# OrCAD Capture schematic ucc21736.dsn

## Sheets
1 PAGE1: size E
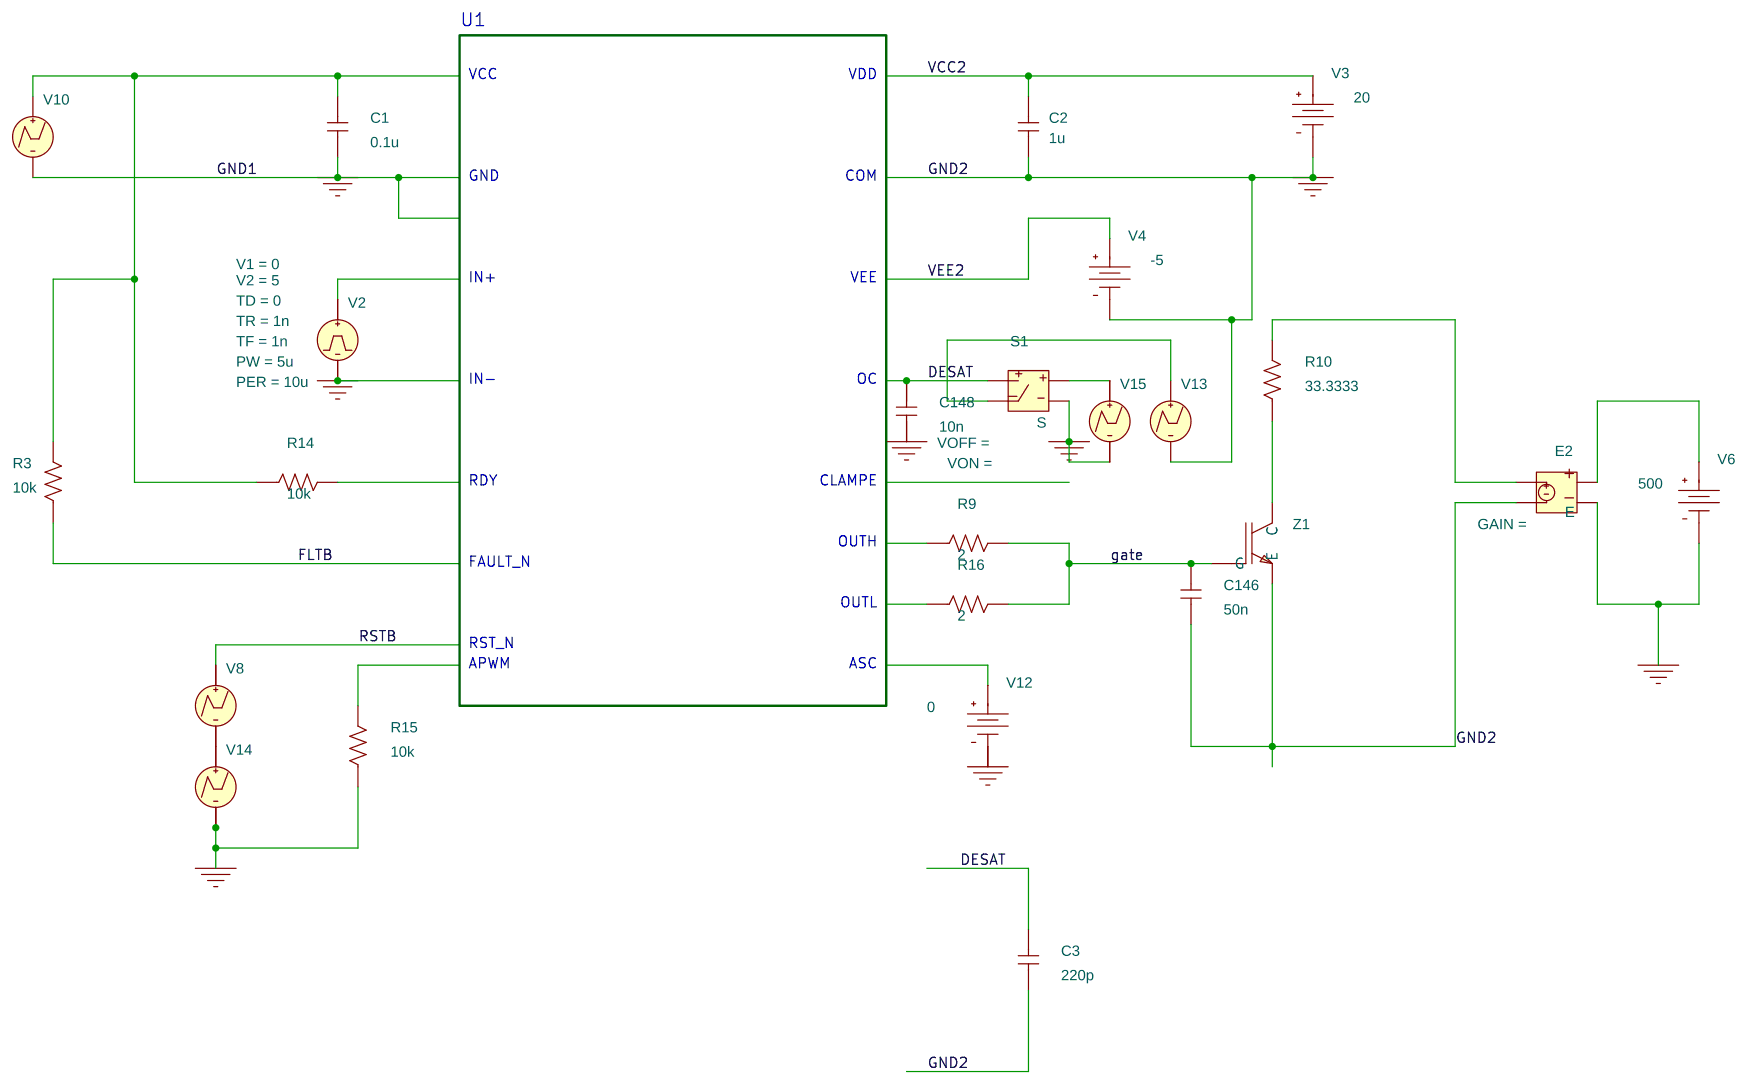
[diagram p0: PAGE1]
2 ISO5851_TRANS: size E; block U1
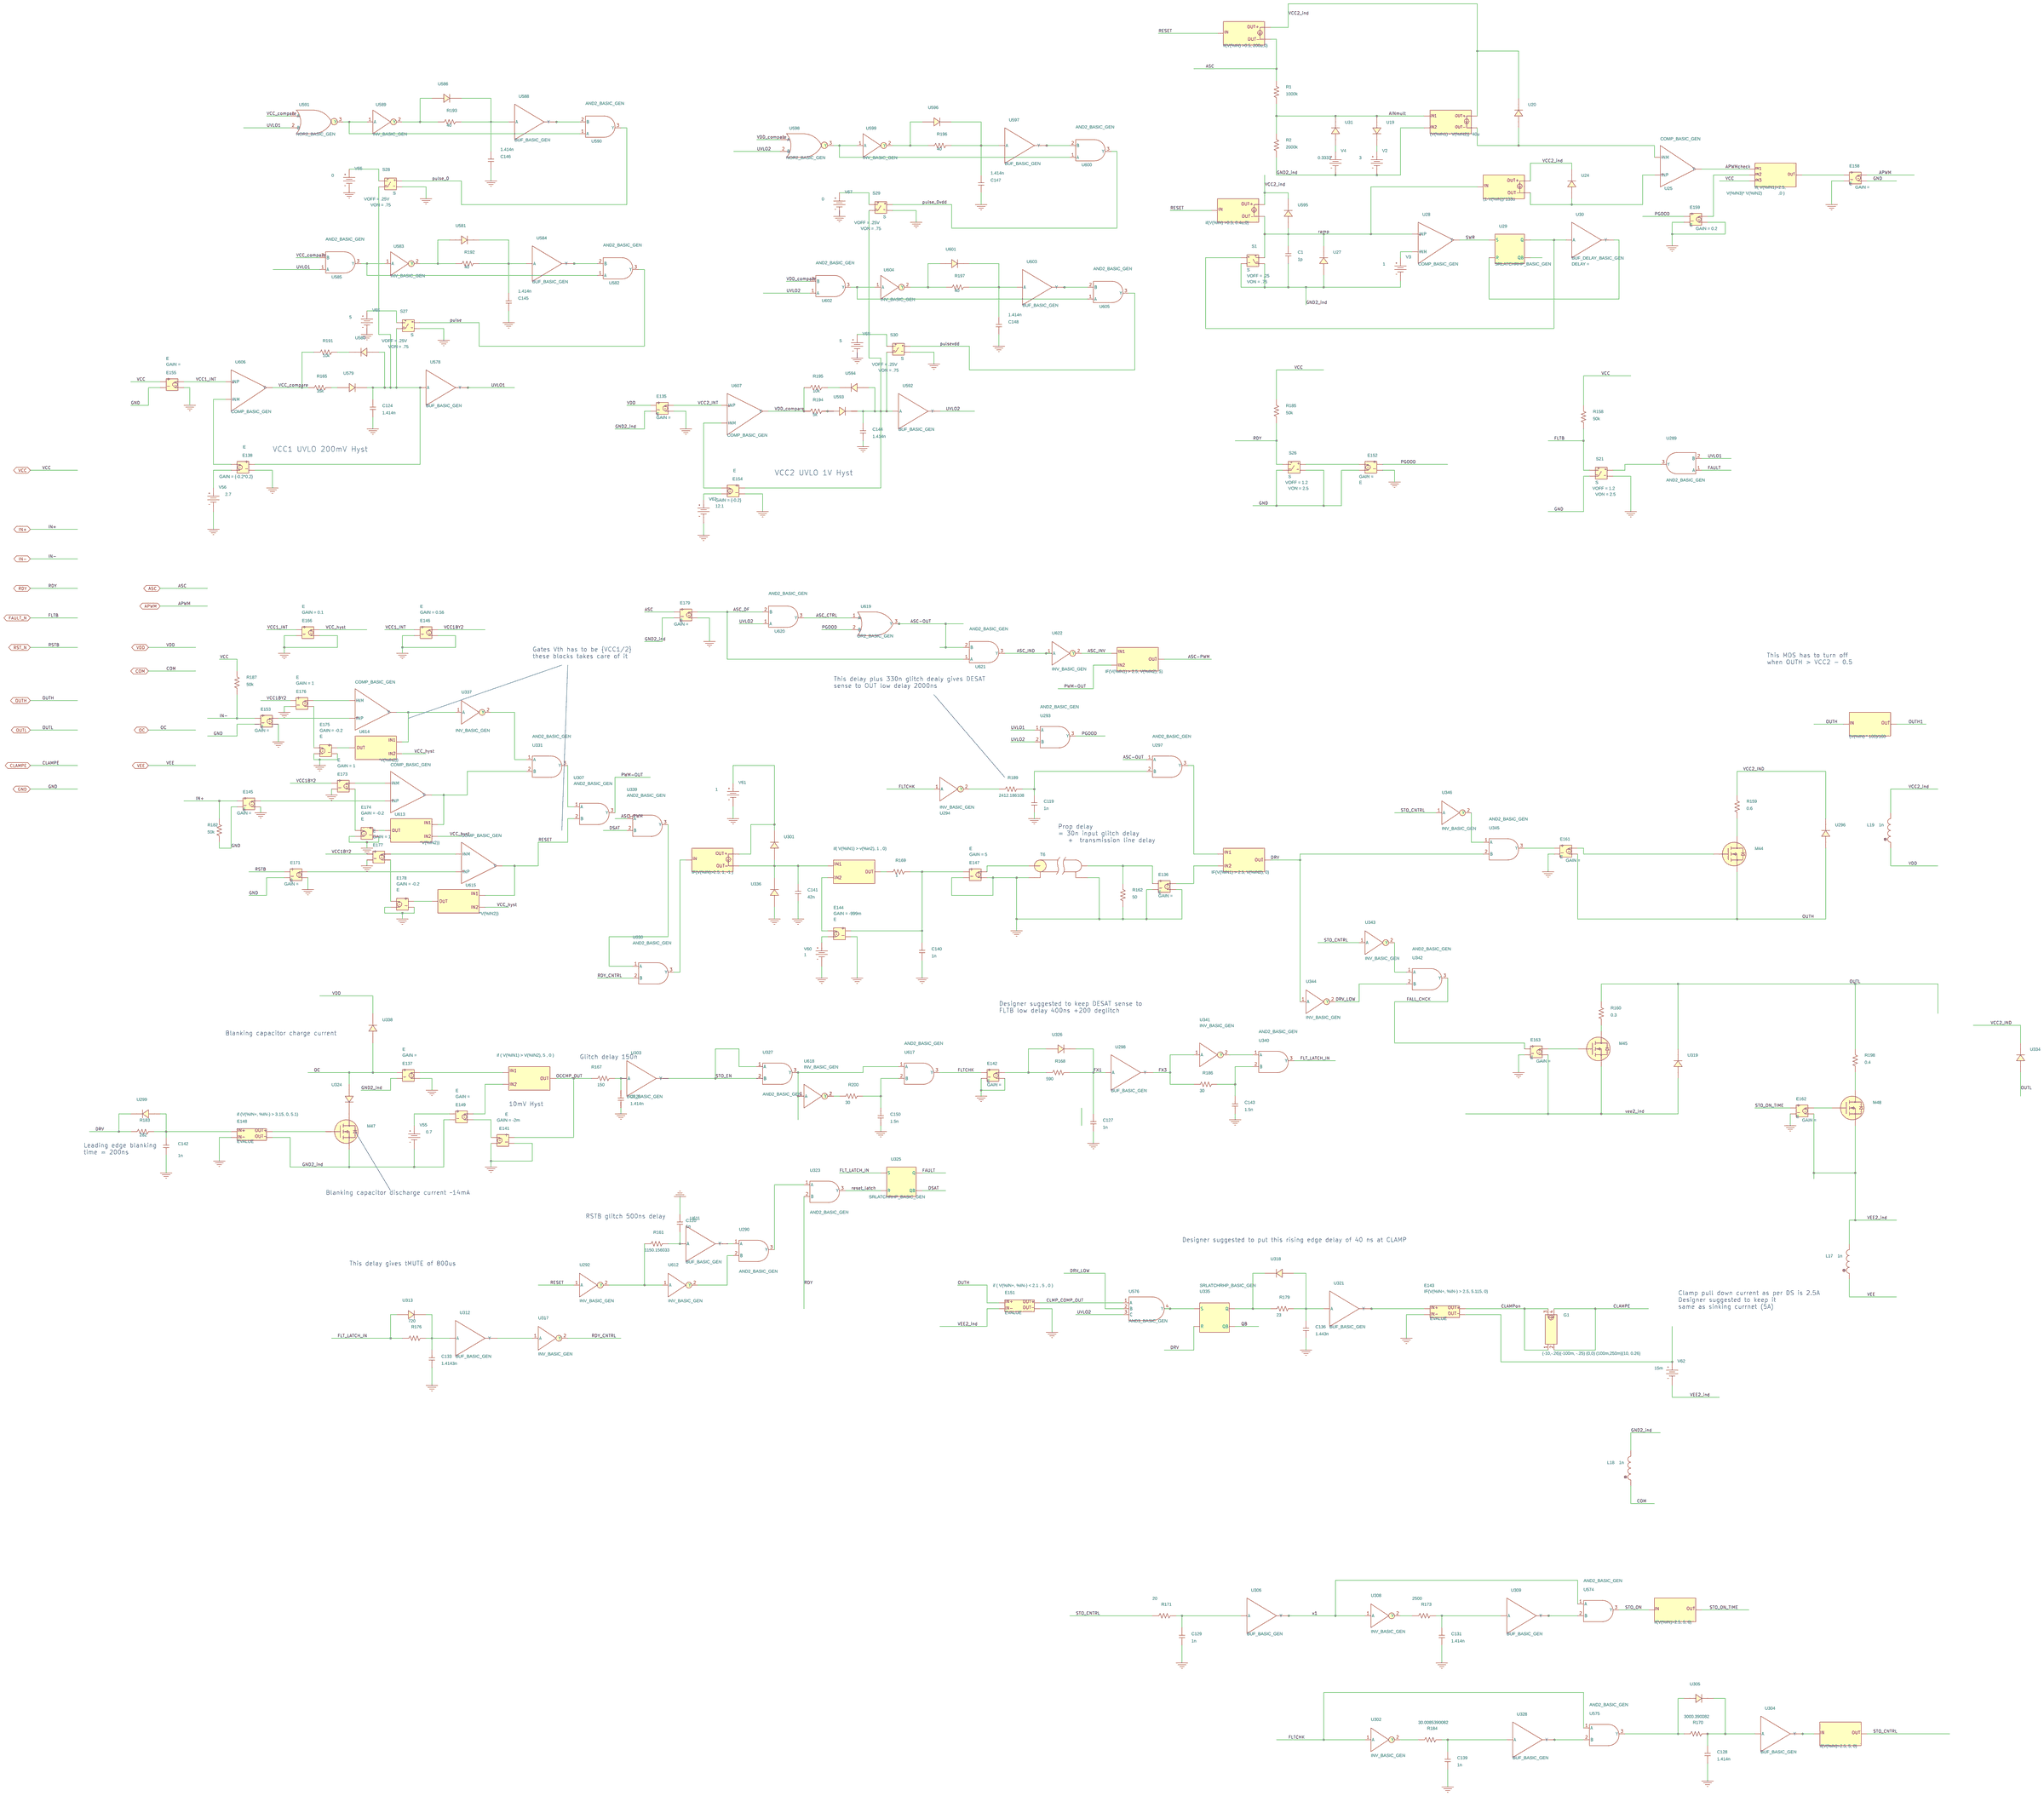
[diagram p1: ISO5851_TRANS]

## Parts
sheet ISO5851_TRANS
ABM2I1  ABM2I
ABM67  ABM2
ABM70  ABM1
ABM71  ABM2
ABM74  ABM1
ABM79  ABM2
ABM80  ABM1
ABM81  ABM3
ABM82  ABM2
ABM83  ABM2
ABM84  ABM2
ABM85  ABM2
ABMII1  ABMII
ABMII2  ABMII
ABMII3  ABMII
ABMII12  ABMII
C1#2  1p  [RAD/CK05]
C119  1n  [RAD/CK05]
C120  1n  [RAD/CK05]
C123  1.414n  [RAD/CK05]
C124  1.414n  [RAD/CK05]
C127  1n  [RAD/CK05]
C128  1.414n  [RAD/CK05]
C129  1n  [RAD/CK05]
C131  1.414n  [RAD/CK05]
C133  1.4143n  [RAD/CK05]
C136  1.443n  [RAD/CK05]
C139  1n  [RAD/CK05]
C140  1n  [RAD/CK05]
C141  42n  [RAD/CK05]
C142  1n  [RAD/CK05]
C143  1.5n  [RAD/CK05]
C144  1.414n  [RAD/CK05]
C145  1.414n  [RAD/CK05]
C146#2  1.414n  [RAD/CK05]
C147  1.414n  [RAD/CK05]
C148#2  1.414n  [RAD/CK05]
C150  1.5n  [RAD/CK05]
E135  E
E136  E
E137  E
E138  E
E141  E
E142  E
E143  EVALUE
E144  E
E145  E
E146  E
E147  E
E148  EVALUE
E149  E
E151  EVALUE
E152  E
E153  E
E154  E
E155  E
E158  E
E159  E
E161  E
E162  E
E163  E
E166  E
E171  E
E173  E
E174  E
E175  E
E176  E
E177  E
E178  E
E179  E
G1  GTABLE
L17  1n  [DISC/.350x.175/LS.200x.100/.034]
L18  1n  [DISC/.350x.175/LS.200x.100/.034]
L19  1n  [DISC/.350x.175/LS.200x.100/.034]
M44  DMG4800LSD
M45  DMG4800LSD
M47  DMG4800LSD
M48  DMG4800LSD
R1  1000k  [AX/RC05]
R2  2000k  [AX/RC05]
R158  50k  [AX/RC05]
R159  0.6  [AX/RC05]
R160  0.3  [AX/RC05]
R161  1150.156033  [AX/RC05]
R162  50  [AX/RC05]
R165  35k  [AX/RC05]
R167  150  [AX/RC05]
R168  590  [AX/RC05]
R169  1  [AX/RC05]
R170  3000.390082  [AX/RC05]
R171  20  [AX/RC05]
R173  2500  [AX/RC05]
R176  720  [AX/RC05]
R179  23  [AX/RC05]
R182  50k  [AX/RC05]
R183  282  [AX/RC05]
R184  30.0085390082  [AX/RC05]
R185  50k  [AX/RC05]
R186  30  [AX/RC05]
R187  50k  [AX/RC05]
R189  2412.186108  [AX/RC05]
R191  10k  [AX/RC05]
R192  40  [AX/RC05]
R193  40  [AX/RC05]
R194  5k  [AX/RC05]
R195  10k  [AX/RC05]
R196  40  [AX/RC05]
R197  40  [AX/RC05]
R198  0.4  [AX/RC05]
R200  30  [AX/RC05]
S1#2  S
S21  S
S26  S
S27  S
S28  S
S29  S
S30  S
T6  T
U19  D_D1
U20  D_D1
U24  D_D1
U25  COMP_BASIC_GEN
U27  D_D1
U28  COMP_BASIC_GEN
U29  SRLATCHRHP_BASIC_GEN
U30  BUF_DELAY_BASIC_GEN
U31  D_D1
U289  AND2_BASIC_GEN
U290  AND2_BASIC_GEN
U292  INV_BASIC_GEN
U293  AND2_BASIC_GEN
U294  INV_BASIC_GEN
U296  D_D1
U297  AND2_BASIC_GEN
U298  BUF_BASIC_GEN
U299  D_D1
U301  D_D1
U302  INV_BASIC_GEN
U303  BUF_BASIC_GEN
U304  BUF_BASIC_GEN
U305  D_D1
U306  BUF_BASIC_GEN
U307  AND2_BASIC_GEN
U308  INV_BASIC_GEN
U309  BUF_BASIC_GEN
U312  BUF_BASIC_GEN
U313  D_D1
U317  INV_BASIC_GEN
U318  D_D1
U319  D_D1
U321  BUF_BASIC_GEN
U323  AND2_BASIC_GEN
U324  D_D1
U325  SRLATCHRHP_BASIC_GEN
U326  D_D1
U327  AND2_BASIC_GEN
U328  BUF_BASIC_GEN
U330  AND2_BASIC_GEN
U331  AND2_BASIC_GEN
U334  D_D1
U335  SRLATCHRHP_BASIC_GEN
U336  D_D1
U337  INV_BASIC_GEN
U338  D_D1
U339  AND2_BASIC_GEN
U340  AND2_BASIC_GEN
U341  INV_BASIC_GEN
U342  AND2_BASIC_GEN
U343  INV_BASIC_GEN
U344  INV_BASIC_GEN
U345  AND2_BASIC_GEN
U346  INV_BASIC_GEN
U574  AND2_BASIC_GEN
U575  AND2_BASIC_GEN
U576  AND3_BASIC_GEN
U578  BUF_BASIC_GEN
U579  D_D1
U580  D_D1
U581  D_D1
U582  AND2_BASIC_GEN
U583  INV_BASIC_GEN
U584  BUF_BASIC_GEN
U585  AND2_BASIC_GEN
U586  D_D1
U588  BUF_BASIC_GEN
U589  INV_BASIC_GEN
U590  AND2_BASIC_GEN
U591  NOR2_BASIC_GEN
U592  BUF_BASIC_GEN
U593  D_D1
U594  D_D1
U595  D_D1
U596  D_D1
U597  BUF_BASIC_GEN
U598  NOR2_BASIC_GEN
U599  INV_BASIC_GEN
U600  AND2_BASIC_GEN
U601  D_D1
U602  AND2_BASIC_GEN
U603  BUF_BASIC_GEN
U604  INV_BASIC_GEN
U605  AND2_BASIC_GEN
U606  COMP_BASIC_GEN
U607  COMP_BASIC_GEN
U611  BUF_BASIC_GEN
U612  INV_BASIC_GEN
U613  COMP_BASIC_GEN
U614  COMP_BASIC_GEN
U615  COMP_BASIC_GEN
U617  AND2_BASIC_GEN
U618  INV_BASIC_GEN
U619  OR2_BASIC_GEN
U620  AND2_BASIC_GEN
U621  AND2_BASIC_GEN
U622  INV_BASIC_GEN
V3#2  VDC
V4#2  VDC
V55  VDC
V56  VDC
V60  VDC
V61  VDC
V62  VDC
V63  VDC
V65  VDC
V66  VDC
V67  VDC
V68  VDC
sheet PAGE1
C1  0.1u  [RAD/CK05]
C2  1u  [RAD/CK05]
C3  220p  [RAD/CK05]
C146  50n  [RAD/CK05]
C148  10n  [cap196]
E2  E
R3  10k  [AX/RC05]
R9  2  [AX/RC05]
R10  33.3333  [AX/RC05]
R14  10k  [AX/RC05]
R15  10k  [AX/RC05]
R16  2  [AX/RC05]
S1  S
V2  VPULSE
V3  VDC
V4  VDC
V6  VDC
V8  VPWL
V10  VPWL
V12  VDC
V13  VPWL
V14  VPWL
V15  VPWL
Z1  IXGA8N100  [TO-263]

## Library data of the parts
ABM2I1 = ABM2_I: EXP1: (V(%IN1) - V(%IN2)) *40u
ABM67 = ABM2: EXP1: if ( V(%IN1) > V(%IN2), 5 , 0 )
ABM70 ABM74 = ABM1: EXP1: if(V(%IN)>2.5, 5, 0)
ABM71 = ABM2: EXP1: if( V(%IN1) > v(%in2), 1 , 0)
ABM79 = ABM2: EXP1: IF(V(%IN1) > 2.5, V(%IN2), 0)
ABM80 = ABM1: EXP1: (V(%IN) * 100)/100
ABM81 = ABM3: EXP1: if( V(%IN1)>2.5,; EXP2: V(%IN3)* V(%IN2); EXP3: ,0 )
ABM82-ABM84 = ABM2: EXP2: *V(%IN2))
ABM85 = ABM2: EXP1: IF(V(%IN1) > 2.5, V(%IN2), 5)
ABMII1 = ABM1_I: EXP1: if(V(%IN) >0.5, 200u,0)
ABMII2 = ABM1_I: EXP1: if(V(%IN) >0.5, 0.4u,0)
ABMII3 = ABM1_I: EXP1: (1-V(%IN))*133u
ABMII12 = ABM1_I: EXP1: IF(V(%IN)>2.5, 1, -1 )
C1 C1#2 C2 C3 C119 C120 C123 C124 C127 C136 C140-C146 C146#2 C147 C148 C148#2 C150 = C
C128 C129 C131 C133 C139 = C: IC: .000001
E2 E135-E137 E142 E145 E149 E152 E153 E155 E158 E161-E163 E171 E179 = E
E138 = E: GAIN: {-0.2*0.2}
E141 = E: GAIN: -2m
E143 = EVALUE: EXPR: IF(V(%IN+, %IN-) > 2.5, 5.115, 0)
E144 = E: GAIN: -999m
E146 = E: GAIN: 0.56
E147 = E: GAIN: 5
E148 = EVALUE: EXPR: if (V(%IN+, %IN-) > 3.15, 0, 5.1)
E151 = EVALUE: EXPR: if ( V(%IN+, %IN-) < 2.1 , 5 , 0 )
E154 = E: GAIN: {-0.2}
E159 = E: GAIN: 0.2
E166 = E: GAIN: 0.1
E173 E176 E177 = E: GAIN: 1
E174 E175 E178 = E: GAIN: -0.2
G1 = GTABLE: TABLE: (-10,-.26)(-100m, -.25) (0,0) (100m,250m)(10, 0.26)
L17-L19 = L
M44 M45 M47 M48 = NAMS20: PSpiceTemplate: X^@REFDES  %D %G %S @MODEL
R1 R2 = r
R3 R9 R10 R14-R16 R158-R162 R165 R167-R171 R173 R176 R179 R182-R187 R189 R191-R198 R200 = R
S1#2 = S: ROFF: 1e9; RON: 1.0m; VOFF: .25; VON: .75
S21 = S: ROFF: 1G; RON: 1m; VOFF: 1.2; VON: 2.5
S26 = S: ROFF: 1m; RON: 1G; VOFF: 1.2; VON: 2.5
S27-S30 = S: VOFF: .25V; VON: .75
T6 = T: TD: 46n; Z0: 50
U19 U20 U24 U27 U31 U296 U299 U301 U305 U313 U318 U319 U324 U326 U334 U336 U338 U579-U581 U586 U593-U596 U601 = D_D1
U25 = COMP_BASIC_GEN_2: VDD: 5; VTHRESH: 2.5
U28 = COMP_BASIC_GEN_5
U29 = SRLATCHRHP_BASIC_GEN
U30 = BUF_DELAY_BASIC_GEN
U289 U290 U293 U297 U307 U323 U327 U330 U331 U339 U340 U342 U345 U574 U575 U582 U585 U590 U600 U602 U605 U617 U620 U621 = AND2_BASIC_GEN: VDD: 5; VTHRESH: 2.5
U292 U294 U302 U308 U317 U337 U341 U343 U344 U346 U583 U589 U599 U604 U612 U618 U622 = INV_BASIC_GEN: VDD: 5; VTHRESH: 2.5
U298 = BUF_BASIC_GEN_5: VDD: 5; VTHRESH: 2.5
U303 = BUF_BASIC_GEN_8: VDD: 5; VTHRESH: 2.5
U304 = BUF_BASIC_GEN_11: VDD: 5; VTHRESH: 2.5
U306 = BUF_BASIC_GEN_13: VDD: 5; VTHRESH: 2.5
U309 = BUF_BASIC_GEN_9: VDD: 5; VTHRESH: 2.5
U312 = BUF_BASIC_GEN_2: VDD: 5; VTHRESH: 2.5
U321 = BUF_BASIC_GEN_10: VDD: 5; VTHRESH: 2.5
U325 = SRLATCHRHP_BASIC_GEN_1: VDD: 5; VTHRESH: 2.5
U328 = BUF_BASIC_GEN_3: VDD: 5; VTHRESH: 2.5
U335 = SRLATCHRHP_BASIC_GEN_2: VDD: 5; VTHRESH: 2.5
U576 = AND3_BASIC_GEN: VDD: 5; VTHRESH: 2500E-3
U578 = BUF_BASIC_GEN_14: VDD: 5; VTHRESH: 2.5
U584 = BUF_BASIC_GEN_12: VDD: 5; VTHRESH: 2.5
U588 = BUF_BASIC_GEN_6: VDD: 5; VTHRESH: 2.5
U591 U598 = NOR2_BASIC_GEN: VDD: 5; VTHRESH: 2.5
U592 = BUF_BASIC_GEN: VDD: 5; VTHRESH: 2.5
U597 = BUF_BASIC_GEN_4: VDD: 5; VTHRESH: 2.5
U603 = BUF_BASIC_GEN_7: VDD: 5; VTHRESH: 2.5
U606 = COMP_BASIC_GEN_1: VDD: 5; VTHRESH: 2.5
U607 = COMP_BASIC_GEN_3: VDD: 5; VTHRESH: 2.5
U611 = BUF_BASIC_GEN_1: VDD: 5; VTHRESH: 2.5
U613 = COMP_BASIC_GEN: VDD: 5; VTHRESH: 2.5
U614 = COMP_BASIC_GEN_4: VDD: 5; VTHRESH: 2.5
U615 = COMP_BASIC_GEN_6: VDD: 5; VTHRESH: 2.5
U619 = OR2_BASIC_GEN: PSpiceTemplate: X^@REFDES %A %B %Y @MODEL PARAMS: ?VDD|VDD=@VDD||VDD=1| ?VSS|VSS=@VSS||VSS=0| ?VTHRESH|VTHRESH=@VTHRESH||VTHRESH=0.5|; VDD: 5
V3#2 V60 V61 = VDC: DC: 1
V4#2 = VDC: DC: 0.3333
V55 = VDC: DC: 0.7
V56 = VDC: DC: 2.7
V62 = VDC: DC: 15m
V63 = VDC: DC: 12.1
V65 V68 = VDC: DC: 5
V12 V66 V67 = VDC: DC: 0
S1 = S
V2 = VPULSE: PER: 10u; PW: 5u; TD: 0; TF: 1n; TR: 1n; V1: 0; V2: 5
V3 = VDC: DC: 20
V4 = VDC: DC: -5
V6 = VDC: DC: 500
V8 = VPWL: PSpiceTemplate: V^@REFDES %+ %- ?DC|DC @DC| ?AC|AC @AC|\n+PWL @T1 @V1 @T2 @V2 #T3/@T3 @V3/ #T4/@T4 @V4/ #T5/@T5 @V5/ #T6/@T6 @V6/ #T7/@T7 @V7/ #T8/@T8 @V8/ #T9/@T9 @V9/ #T10/@T10 @V10/; T1: 0; T2: 44.4u; T3: 44.401u; T4: 44.8u; T5: 44.801u; T6: 65u; T7: 65.001u; T8: 85u; V1: 5; V2: 5; V3: 0; V4: 0; V5: 5; V6: 5; V7: 0; V8: 0
V10 = VPWL: PSpiceTemplate: V^@REFDES %+ %- ?DC|DC @DC| ?AC|AC @AC|\n+PWL @T1 @V1 @T2 @V2 #T3/@T3 @V3/ #T4/@T4 @V4/ #T5/@T5 @V5/ #T6/@T6 @V6/ #T7/@T7 @V7/ #T8/@T8 @V8/ #T9/@T9 @V9/ #T10/@T10 @V10/; T1: 0; T2: 1u; V1: 0; V2: 5
V13 = VPWL: T1: 40u; T2: 45u; V1: 0; V2: 1
V14 = VPWL: PSpiceTemplate: V^@REFDES %+ %- ?DC|DC @DC| ?AC|AC @AC|\n+PWL @T1 @V1 @T2 @V2 #T3/@T3 @V3/ #T4/@T4 @V4/ #T5/@T5 @V5/ #T6/@T6 @V6/ #T7/@T7 @V7/ #T8/@T8 @V8/ #T9/@T9 @V9/ #T10/@T10 @V10/; T1: 0; T2: 66u; T3: 66.001u; V1: 0; V2: 0; V3: 5
V15 = VPWL: T1: 45u; T2: 46u; T3: 46.01u; V1: 1; V2: 1; V3: 0
Z1 = IXGA8N100

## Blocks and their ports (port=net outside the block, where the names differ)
U1 = schematic UCC21736_TRANS, on sheet PAGE1: RDY=N16432057, IN+=N16431787, IN-=0, OUTH=N16432123, OUTL=N16432177, FAULT_N=FLTB, RST_N=RSTB, GND=0, VEE=VEE2, COM=0, VDD=VCC2, VCC=N16431547, OC=DESAT, APWM=N16432213, CLAMPE=N16432063, ASC=N16432223

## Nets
U1/VCC1_INT: E146.1 E155.3 E166.1 U606.INP
U1/VCC1BY2: E146.3 E173.1 E176.1 E177.1
U1/VCC2_IND: ABM2I1.3(OUT+) ABMII1.2(out+) ABMII2.2(out+) ABMII3.2(out+) L19.2 R159.2 U20.2(C) U24.2(C) U296.2(C) U334.2(C) U595.2(C)
U1/VCC2_INT: E135.3 U607.INP
U1/VCC_compare: R165.1 R191.1 U585.2(B) U591.1(A) U606.Y
U1/VCC_hyst: ABM82.2(IN2) ABM83.2(IN2) ABM84.2(IN2) E166.3
U1/VDD_compare: R194.1 R195.1 U598.1(A) U602.2(B) U607.Y
U1/VEE2_ind: E151.2(IN-) E162.4 E163.4 L17.2 M45.3(S) M48.3(S) U319.1(A) V62.1(-)
VCC2: C2.2 E135.1 L19.1 U338.2(C) V3.0(+)
VEE2: L17.1 V4.0(+)
0: C1.1 C2.1 C3.1 C119.1 C120.1 C123.1 C124.1 C127.1 C128.1 C129.1 C131.1 C133.1 C136.1 C139.1 C140.1 C141.2 C142.1 C143.1 C144.1 C145.2 C146.2 C146#2.2 C147.2 C148.2 C148#2.2 C150.1 E2.2 E2.4 E135.4 E136.2 E136.4 E137.4 E138.2 E141.2 E141.4 E142.2 E142.4 E143.2(IN-) E144.2 E145.2 E145.4 E146.2 E146.4 E147.2 E147.4 E148.2(IN-) E151.4(OUT-) E152.2 E152.4 E153.1 E153.2 E153.4 E154.2 E155.2 E155.4 E158.2 E158.4 E159.2 E159.4 E161.2 E162.2 E163.2 E166.2 E166.4 E171.2 E171.4 E173.2 E174.2 E174.4 E175.2 E175.4 E176.2 E177.2 E178.2 E178.4 E179.4 L18.1 R15.1 R162.1 R182.1 R187.1 S1.1(2) S21.1(2) S21.3(4) S26.1(2) S26.3(4) S27.1(2) S28.1(2) S29.1(2) S30.1(2) T6.2(A-) T6.4(B-) U336.1(A) V2.2(-) V3.1(-) V4.1(-) V6.1(-) V10.2(-) V12.1(-) V13.2(-) V14.2(-) V15.2(-) V56.1(-) V60.1(-) V61.1(-) V63.1(-) V65.1(-) V66.1(-) V67.1(-) V68.1(-) Z1.3(E)
DESAT: C3.2 C148.1 E137.1 S1.2(3) U324.1(A) U338.1(A)
FLTB: R3.1 R158.1 S21.2(3)
gate: C146.1 R9.2 R16.2 Z1.1(G)
RSTB: E171.1 V8.1(+)
U1/AINmult: ABM2I1.1(IN1) R1.1 R2.2 U19.1(A) U31.2(C)
U1/APWMcheck: ABM81.1(IN1) U25.Y
U1/ASC-OUT: U297.1(A) U619.3(Y) U621.2(B)
U1/ASC-PWM: ABM85.3(OUT) U339.1(A)
U1/ASC_CTRL: U619.1(A) U620.3(Y)
U1/ASC_DF: E179.3 U620.2(B) U621.1(A)
U1/ASC_IND: U621.3(Y) U622.1(A)
U1/ASC_INV: ABM85.1(IN1) U622.2(Y)
U1/CLAMPon: E143.3(OUT+) G1.1(IN+) G1.3(OUT+)
U1/CLMP_COMP_OUT: E151.3(OUT+) U576.1(A)
U1/DRV: ABM79.3(OUT) R183.1 U299.2(C) U335.R U344.1(A) U345.2(B)
U1/DRV_LOW: U342.2(B) U344.2(Y) U576.2(B)
U1/DSAT: U325.QB U339.2(B)
U1/FALL_CHCK: E163.1 U342.3(Y)
U1/FAULT: U289.1(A) U325.Q
U1/FLT_LATCH_IN: R176.1 U313.1(A) U325.S U340.3(Y)
U1/FLTCHK: E142.1 U294.1(A) U302.1(A) U575.1(A) U617.3(Y)
U1/FX1: C127.2 R168.2 U298.A U326.2(C)
U1/FX3: R186.1 U298.Y U341.1(A)
U1/OCCMP_OUT: ABM67.3(OUT) E141.1 R167.1
U1/OUTH1: ABM80.2(OUT)
U1/PGOOD: E152.1 E159.1 U293.3(Y) U619.2(B)
U1/pulse: S27.0(1) U582.3(Y)
U1/pulse_0: S28.0(1) U590.3(Y)
U1/pulse_0vdd: S29.0(1) U600.3(Y)
U1/pulsevdd: S30.0(1) U605.3(Y)
U1/PWM-OUT: ABM85.2(IN2) U307.3(Y)
U1/QB: U335.QB
U1/ramp: ABMII2.3(out-) ABMII3.1(IN) C1#2.1 S1#2.2(3) U27.2(C) U28.INP U595.1(A)
U1/RDY_CNTRL: U317.2(Y) U330.2(B)
U1/RESET: ABM84.1(IN1) ABMII1.1(IN) ABMII2.1(IN) U292.1(A) U307.2(B) U615.Y
U1/reset_latch: U323.3(Y) U325.R
U1/STO_CNTRL: ABM70.2(OUT) R171.1 U343.1(A) U346.1(A)
U1/STO_EN: U303.Y U327.1(A) U327.2(B)
U1/STO_ON: ABM74.1(IN) U574.3(Y)
U1/STO_ON_TIME: ABM74.2(OUT) E162.1
U1/SWR: U28.Y U29.S
U1/UVLO1: U289.2(B) U293.1(A) U578.Y U585.1(A) U591.2(B)
U1/UVLO2: U293.2(B) U576.3(C) U592.Y U598.2(B) U602.1(A) U620.1(A)
U1/x1: U306.Y U308.1(A) U574.1(A)
N16431547: ABM81.3(IN3) C1.2 E155.1 R3.2 R14.1 R158.2 R185.2 R187.2 V10.1(+)
N16431787: ABM2I1.2(IN2) C1#2.2 E135.2 E137.2 E145.1 E148.4(OUT-) E149.2 E179.2 L18.2 M47.3(S) R2.1 R182.2 S1#2.1(2) S1#2.3(4) U27.1(A) V2.1(-) V3#2.1(-) V4#2.1(-) V55.1(-)
N16431855: E2.3 R10.2
N16431941: E2.1 V6.0(+)
N16431955: R10.1 Z1.2(C)
N16432057: R14.2 R185.1 S26.2(3) U323.2(B)
N16432063: G1.2(IN-) G1.4(OUT-)
N16432123: ABM80.1(IN) E151.1(IN+) E161.4 M44.3(S) R9.1 U296.1(A)
N16432177: R16.1 R160.2 R198.2 U319.2(C) U334.1(A)
N16432213: E158.3 R15.2
N16432223: ABMII1.3(out-) E179.1 R1.2 V12.0(+)
N16434692: S1.3(4) V13.1(+)
N16434803: S1.0(1) V15.1(+)
N16442950: V8.2(-) V14.1(+)
N19072178: M47.1(D) U324.2(C)
U1/N19023094: R193.1 U586.1(A) U589.2(Y)
U1/N19023099: C146#2.1 R193.2 U586.2(C) U588.A
U1/N19023211: U589.1(A) U590.1(A) U591.3(Y)
U1/N19023228: U588.Y U590.2(B)
U1/N19023233: R196.1 U596.1(A) U599.2(Y)
U1/N19023238: C147.1 R196.2 U596.2(C) U597.A
U1/N19023288: ABM2I1.4(OUT-) U20.1(A) U25.INM
U1/N19023357: U598.3(Y) U599.1(A) U600.1(A)
U1/N19023374: U597.Y U600.2(B)
U1/N19023379: U31.1(A) V4#2.0(+)
U1/N19023382: U19.2(C) V2.0(+)
U1/N19023480: S28.2(3) V66.0(+)
U1/N19023548: ABMII3.3(out-) U24.1(A) U25.INP
U1/N19023552: ABM81.2(IN2) E159.3
U1/N19023557: ABM81.4(OUT) E158.1
U1/N19023593: C124.2 E138.1 S27.3(4) S28.3(4) U578.A U579.2(C) U580.1(A)
U1/N19023619: S29.2(3) V67.0(+)
U1/N19023696: C144.2 E154.1 S29.3(4) S30.3(4) U592.A U593.2(C) U594.1(A)
U1/N19023822: R192.1 U581.1(A) U583.2(Y)
U1/N19023827: C145.1 R192.2 U581.2(C) U584.A
U1/N19023836: S1#2.0(1) U29.Q U30.A
U1/N19023842: U29.R U30.Y
U1/N19023931: U28.INM V3#2.0(+)
U1/N19023980: U582.1(A) U583.1(A) U585.3(Y)
U1/N19023998: U582.2(B) U584.Y
U1/N19024003: R197.1 U601.1(A) U604.2(Y)
U1/N19024008: C148#2.1 R197.2 U601.2(C) U603.A
U1/N19024097: U602.3(Y) U604.1(A) U605.1(A)
U1/N19024115: U603.Y U605.2(B)
U1/N19024167: S27.2(3) V65.0(+)
U1/N19024234: S30.2(3) V68.0(+)
U1/N19024299: R191.2 U580.2(C)
U1/N19024448: R165.2 U579.1(A)
U1/N19024473: R195.2 U594.2(C)
U1/N19024504: E138.3 U606.INM
U1/N19024592: R194.2 U593.1(A)
U1/N19024628: E154.3 U607.INM
U1/N19024743: E152.3 S26.0(1)
U1/N19024765: S21.0(1) U289.3(Y)
U1/N19024774: E138.4 V56.0(+)
U1/N19024858: E154.4 V63.0(+)
U1/N19025119: E176.3 U614.INM
U1/N19025138: E175.3 E176.4
U1/N19025158: ABM83.1(IN1) U337.1(A) U614.Y
U1/N19025166: U331.1(A) U337.2(Y)
U1/N19025185: E153.3 U614.INP
U1/N19025277: ABM83.3(OUT) E175.1
U1/N19025345: U307.1(A) U331.3(Y)
U1/N19025348: ABMII12.2(out+) U301.2(C) V61.0(+)
U1/N19025373: ABM82.1(IN1) U331.2(B) U613.Y
U1/N19025378: C119.2 R189.2 U297.2(B)
U1/N19025423: E173.3 U613.INM
U1/N19025457: E173.4 E174.3
U1/N19025464: R189.1 U294.2(Y)
U1/N19025515: E145.3 U613.INP
U1/N19025602: U345.1(A) U346.2(Y)
U1/N19025633: M44.1(D) R159.1
U1/N19025673: U330.1(A) U339.3(Y)
U1/N19025693: ABM82.3(OUT) E174.1
U1/N19025827: E161.1 U345.3(Y)
U1/N19025832: E161.3 M44.2(G)
U1/N19025845: E177.3 U615.INM
U1/N19025881: E177.4 E178.3
U1/N19025884: ABMII12.1(IN) U330.3(Y)
U1/N19025889: ABM71.1(IN1) ABMII12.3(out-) C141.1 U301.1(A) U336.2(C)
U1/N19025962: E147.3 T6.1(A+)
U1/N19025967: E136.1 R162.2 T6.3(B+)
U1/N19025976: ABM79.2(IN2) E136.3
U1/N19025989: E171.3 U615.INP
U1/N19025992: ABM71.3(OUT) R169.1
U1/N19025995: C140.2 E144.1 E147.1 R169.2
U1/N19026015: ABM71.2(IN2) E144.3
U1/N19026125: ABM84.3(OUT) E178.1
U1/N19026221: E144.4 V60.0(+)
U1/N19026246: U342.1(A) U343.2(Y)
U1/N19026396: M45.1(D) R160.1
U1/N19026467: E142.3 R168.1 U326.1(A)
U1/N19026489: E163.3 M45.2(G)
U1/N19026519: U340.1(A) U341.2(Y)
U1/N19026630: U327.3(Y) U617.1(A) U618.1(A)
U1/N19026658: C143.2 R186.2 U340.2(B)
U1/N19026693: ABM67.1(IN1) E137.3
U1/N19026764: C123.2 R167.2 U303.A
U1/N19026775: C150.2 R200.2 U617.2(B)
U1/N19026806: ABM67.2(IN2) E149.3
U1/N19026881: R200.1 U618.2(Y)
U1/N19026934: C142.2 E148.1(IN+) R183.2 U299.1(A)
U1/N19026938: E149.1 V55.0(+)
U1/N19026984: E141.3 E149.4
U1/N19027052: E148.3(OUT+) M47.2(G)
U1/N19027309: U290.3(Y) U323.1(A)
U1/N19027436: C120.2 R161.2 U611.A
U1/N19027481: R161.1 U292.2(Y) U612.1(A)
U1/N19027486: U290.1(A) U611.Y
U1/N19027500: U290.2(B) U612.2(Y)
U1/N19027551: R179.1 U318.2(C) U335.Q
U1/N19027556: C136.2 R179.2 U318.1(A) U321.A
U1/N19027689: U335.S U576.4(Y)
U1/N19027705: E143.1(IN+) U321.Y
U1/N19027732: C133.2 R176.2 U312.A U313.2(C)
U1/N19027746: E143.4(OUT-) V62.0(+)
U1/N19027831: U312.Y U317.1(A)
U1/N19028028: C129.2 R171.2 U306.A
U1/N19028043: R173.1 U308.2(Y)
U1/N19028046: C131.2 R173.2 U309.A
U1/N19028053: U309.Y U574.2(B)
U1/N19028115: R170.1 U305.1(A) U575.3(Y)
U1/N19028119: C128.2 R170.2 U304.A U305.2(C)
U1/N19028213: ABM70.1(IN) U304.Y
U1/N19028227: R184.1 U302.2(Y)
U1/N19028230: C139.2 R184.2 U328.A
U1/N19028237: U328.Y U575.2(B)
U1/N19045940: M48.1(D) R198.1
U1/N19045968: E162.3 M48.2(G)
U1/N19062042: ABM79.1(IN1) U297.3(Y)

Not connected (* = marked no-connect by the designer): U29 QB

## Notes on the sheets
sheet 2
- VCC1 UVLO 200mV Hyst
- VCC2 UVLO 1V Hyst
- Gates Vth has to be {VCC1/2}
  these blocks takes care of it
- This MOS has to turn off
  when OUTH > VCC2 - 0.5
- This delay plus 330n glitch dealy gives DESAT
  sense to OUT low delay 2000ns
- Prop delay
  = 30n input glitch delay
     +  transmission line delay
- Designer suggested to keep DESAT sense to
  FLTB low delay 400ns +200 deglitch
- Blanking capacitor charge current
- Glitch delay 150n
- 10mV Hyst
- Leading edge blanking
  time = 200ns
- Blanking capacitor discharge current ~14mA
- RSTB glitch 500ns delay
- Designer suggested to put this rising edge delay of 40 ns at CLAMP
- This delay gives tMUTE of 800us
- Clamp pull down current as per DS is 2.5A
  Designer suggested to keep it
  same as sinking currnet (5A)
